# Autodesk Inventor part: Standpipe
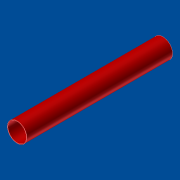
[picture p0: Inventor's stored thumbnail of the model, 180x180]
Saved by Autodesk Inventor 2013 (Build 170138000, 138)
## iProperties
Shininess: 41.0
Length Units: 11269
Angle Units: 11279
Time Units: 11290
Mass Units: 11283
Length Display Precision: 3
Angle Display Precision: 2
Created: 2001-04
Part Number: Standpipe
Material: Standard
Document SubType Name: Modellieren
Designer: dl
Density: 1 g/cm^3
Density: 0.0
Volumn: 0.0
Area: 0.0
PropertySet Name: Model Information
Control State: 0
Master: False
Checked Out: False
Author: dl
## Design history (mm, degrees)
body "Solid1"
sketch "Sketch1"
  geometry: C1 r 21 at (17.102, 39.308); C2 r 20 at (17.102, 39.308)
  constraints: 2 centre point, 1 coincident
  dimensions: "d0" = 42 diameter of C1; "d1" = 1 radial gap between concentric circles of C1 C2
extrude "Extrusion1" new body sketch "Sketch1" distance "d2" = 314; taper "d3" = 0 deg
